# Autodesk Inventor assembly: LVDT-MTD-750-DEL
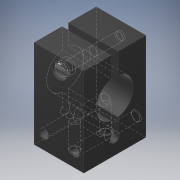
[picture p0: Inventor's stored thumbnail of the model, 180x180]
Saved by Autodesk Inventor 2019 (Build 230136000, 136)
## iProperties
Created: 2018-06
Part Number: LVDT-MTD-750-DEL
Document SubType Name: Assembly
Designer: Justin
Author: Justin
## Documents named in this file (3)
- C:\Users\Justin\Documents\CAD Drawings\The Sensor Connection\3D\LVDT\LVDT-MTD-750-DEL.iam
- C:\Users\Justin\Documents\CAD Drawings\The Sensor Connection\3D\LVDT\LVDT-MTD-750-DEL.ipt
- C:\Users\Justin\Documents\CAD Drawings\The Sensor Connection\3D\LVDT\LVDT-MTD-750-DEL_(#8 SCREW).ipt
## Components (2 placed, 2 different names)
1. LVDT-MTD-750-DEL:1 — Mate:2, Mate:3
2. LVDT-MTD-750-DEL_(#8 SCREW):1 — Mate:2, Mate:3
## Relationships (2: Mate 2)
- Mate:2: LVDT-MTD-750-DEL:1 ↔ LVDT-MTD-750-DEL_(#8 SCREW):1
- Mate:3: LVDT-MTD-750-DEL:1 ↔ LVDT-MTD-750-DEL_(#8 SCREW):1
